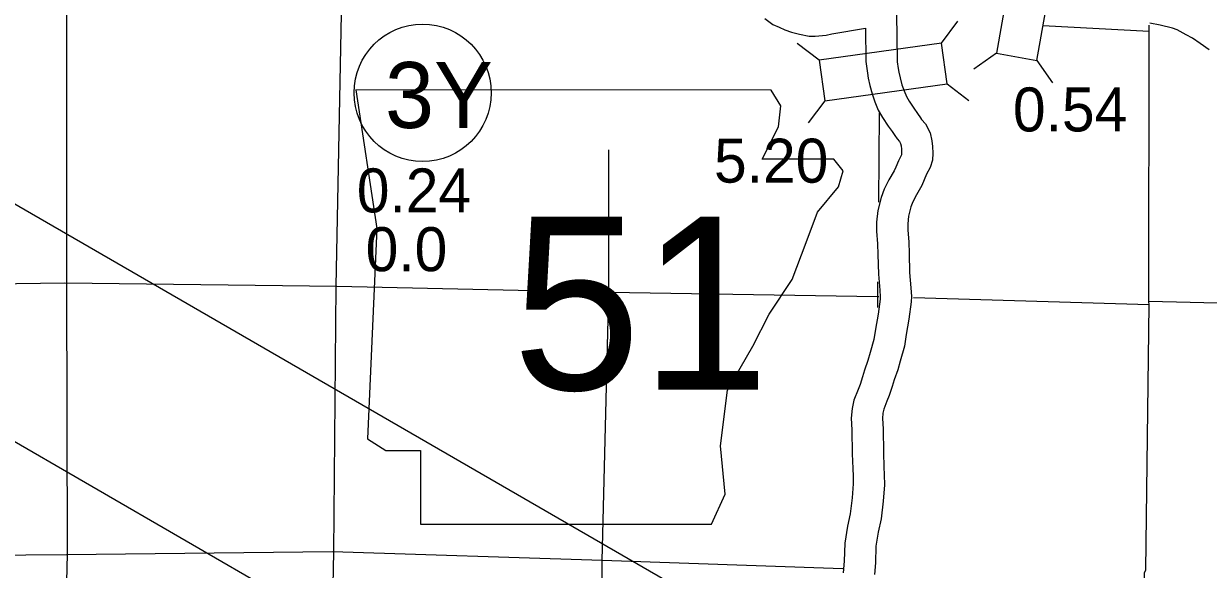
# Model space of a CAD drawing. Extents: x 369523 to 838377, y 495025 to 936819.
# Drawn here: x 618049 to 640839, y 806739 to 817222 of the extents above; entities that cross this region are included whole.
import ezdxf

# ---------------------------------------------------------------- set-up
doc = ezdxf.new("R2010")
doc.units = 0
for name, color, linetype in [('21', 7, 'Continuous'), ('22', 7, 'Continuous'), ('DSN_BRDG_Annotation', 7, 'Continuous'), ('DSN_DRFT_Common-Line', 7, 'Continuous'), ('DSN_DRFT_Junk-No-Plot', 7, 'Continuous'), ('Level 1', 7, 'Continuous'), ('Level 15', 7, 'Continuous'), ('Level 21', 7, 'Continuous'), ('Level 22', 7, 'Continuous')]:
    doc.layers.add(name, color=color, linetype=linetype)

msp = doc.modelspace()

# ---------------------------------------------------------------- linework, layer by layer
at = {"layer": '21'}
for p, q in [((459282, 905322), (715348, 757482)), ((708796, 756692), (471020, 893972))]:
    msp.add_line(p, q, dxfattribs=at)
at = {"layer": '22'}
msp.add_lwpolyline([(624440, 815952), (624840, 813287), (624662, 809246), (625018, 809024), (625684, 809024), (625684, 807603), (631279, 807603), (631546, 808180), (631457, 809113), (631590, 810179), (632079, 811023), (632390, 811644), (632834, 812310), (633100, 813021), (633322, 813598), (633722, 814087), (633811, 814398), (633633, 814620), (632256, 814620), (632567, 815241), (632612, 815641), (632427, 815948)], close=True, dxfattribs=at)
at = {"layer": 'DSN_DRFT_Common-Line'}
msp.add_circle((625724, 815895), 1320, dxfattribs=at)
at = {"layer": 'Level 1'}
for points in [[(634835, 817843), (634850, 816531), (634855, 816487), (634875, 816359), (634885, 816288), (634912, 816180), (634945, 816048), (634986, 815933), (635032, 815823), (635082, 815733), (635171, 815596), (635245, 815496), (635299, 815416), (635322, 815384), (635395, 815300), (635489, 815124), (635520, 814972), (635532, 814864), (635540, 814732), (635530, 814597), (635490, 814461), (635420, 814328), (635373, 814219), (635326, 814116), (635222, 813937), (635153, 813797), (635116, 813703), (635073, 813527), (635056, 813379), (635058, 813262), (635077, 813022), (635083, 812805), (635090, 812444), (635118, 812145), (635128, 811982), (635124, 811878), (635080, 811546), (635027, 811251), (634991, 811028), (634912, 810741), (634863, 810569), (634798, 810381), (634759, 810252), (634702, 810081), (634657, 809972), (634596, 809814), (634580, 809741), (634572, 809634), (634582, 809439), (634587, 808975), (634598, 808705), (634606, 808551), (634609, 808364), (634584, 808050), (634542, 807708), (634488, 807455), (634444, 807185), (634435, 806860), (634414, 806639)], [(632308, 817321), (632464, 817206), (632585, 817153), (632693, 817104), (632820, 817057), (632974, 817023), (633157, 816982), (633274, 816984), (633349, 816992), (633485, 817000), (633593, 817028), (634243, 817136)], [(640854, 816722), (640683, 816843), (640536, 816944), (640411, 817011), (640299, 817072), (640239, 817103), (640152, 817135), (639915, 817195), (639715, 817233)], [(634243, 817136), (634251, 816495), (634261, 816407), (634282, 816272), (634295, 816175), (634330, 816036), (634370, 815873), (634426, 815718), (634490, 815562), (634568, 815422), (634677, 815254), (634755, 815149), (634808, 815072), (634851, 815012), (634896, 814959), (634919, 814917), (634927, 814877), (634934, 814813), (634939, 814737), (634936, 814705), (634931, 814687), (634878, 814586), (634826, 814464), (634793, 814393), (634692, 814220), (634604, 814040), (634542, 813884), (634482, 813634), (634455, 813408), (634458, 813233), (634477, 812990), (634483, 812790), (634491, 812411), (634520, 812099), (634527, 811973), (634526, 811928), (634487, 811639), (634436, 811351), (634404, 811156), (634334, 810903), (634290, 810749), (634227, 810566), (634187, 810434), (634139, 810290), (634100, 810193), (634020, 809988), (633985, 809828), (633971, 809642), (633982, 809421), (633987, 808960), (633999, 808678), (634006, 808531), (634009, 808383), (633987, 808111), (633949, 807807), (633898, 807565), (633845, 807241), (633836, 806897), (633814, 806672)]]:
    msp.add_lwpolyline(points, dxfattribs=at)
at = {"layer": 'Level 15'}
msp.add_lwpolyline([(639605, 795302), (639614, 796097), (639603, 796141), (639603, 801405), (639617, 801574), (639609, 806673), (639635, 806730), (639701, 811822), (639697, 811886), (639701, 817074), (639702, 817195)], dxfattribs=at)
at = {"layer": 'Level 21'}
for p, q in [((635704, 816851), (636022, 817272)), ((633350, 816523), (632929, 816841)), ((636761, 816654), (636329, 816351)), ((637541, 816516), (637844, 816083)), ((635813, 816066), (636234, 815748)), ((633459, 815739), (633141, 815317))]:
    msp.add_line(p, q, dxfattribs=at)
for points in [[(637541, 816516), (637954, 818856), (637175, 818993), (636761, 816654)], [(633459, 815739), (635813, 816066), (635704, 816851), (633350, 816523)]]:
    msp.add_lwpolyline(points, close=True, dxfattribs=at)
at = {"layer": 'Level 22'}
for points in [[(618849, 822243), (618876, 817454), (618873, 812234), (618886, 807031), (618756, 801748), (618602, 796403), (618555, 791305)], [(623823, 791181), (623850, 796494), (623904, 801631), (624018, 807069), (624063, 812181), (624162, 817411), (624142, 819167)], [(639701, 817074), (637656, 817184)], [(634499, 813795), (634516, 815509)], [(629300, 814799), (629297, 812056), (629169, 806899), (629161, 801565), (629098, 796252), (629043, 791825)], [(634498, 811972), (634474, 811973), (629307, 812060), (624075, 812174), (618843, 812237), (613709, 812165)], [(634479, 811770), (634480, 811983), (634483, 812260)], [(639701, 811822), (635169, 811953)], [(644993, 811758), (639697, 811886)], [(633808, 806749), (629181, 806908), (623992, 807076), (618874, 807016), (613368, 806973)]]:
    msp.add_lwpolyline(points, dxfattribs=at)

# ---------------------------------------------------------------- texts
at = {"layer": '22'}
msp.add_text('51', height=3326.4, dxfattribs=at).set_placement((627448, 810189))
at = {"layer": 'DSN_BRDG_Annotation'}
for s, p in [('0.24', (624458, 813596)), ('0.0', (624628, 812467))]:
    msp.add_text(s, height=844.8, dxfattribs=at).set_placement(p)
at = {"layer": 'DSN_DRFT_Common-Line'}
msp.add_text('3Y', height=1267.2, dxfattribs=at).set_placement((625001, 815218))
at = {"layer": 'DSN_DRFT_Junk-No-Plot'}
for s, p in [('0.54', (637080, 815152)), ('5.20', (631330, 814168))]:
    msp.add_text(s, height=844.8, dxfattribs=at).set_placement(p)

doc.saveas('drawing.dxf')
